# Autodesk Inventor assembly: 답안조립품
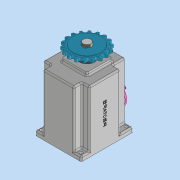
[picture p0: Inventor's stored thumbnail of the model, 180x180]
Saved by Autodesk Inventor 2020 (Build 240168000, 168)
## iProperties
Created: 2022-01
Part Number: 답안조립품
Document SubType Name: Assembly
Designer: user
Author: user
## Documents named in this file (16)
- C:\Users\user\Desktop\720112V1009\답안조립품.iam
- C:\Users\user\Desktop\720112V1009\멈춤나사 M3.ipt
- C:\Users\user\Desktop\720112V1009\메인 축.ipt
- C:\Users\user\Desktop\720112V1009\베어링 608.ipt
- C:\Users\user\Desktop\720112V1009\베어링 6003.ipt
- C:\Users\user\Desktop\720112V1009\본체.ipt
- C:\Users\user\Desktop\720112V1009\볼트 M4 x 10.ipt
- C:\Users\user\Desktop\720112V1009\부시.ipt
- C:\Users\user\Desktop\720112V1009\상부 캡.ipt
- C:\Users\user\Desktop\720112V1009\서브 축.ipt
- C:\Users\user\Desktop\720112V1009\스프로킷.ipt
- C:\Users\user\Desktop\720112V1009\슬라이더.ipt
- C:\Users\user\Desktop\720112V1009\오일 실 8 x 22 x 7.ipt
- C:\Users\user\Desktop\720112V1009\오일 실 17 x 32 x 8.ipt
- C:\Users\user\Desktop\720112V1009\커버.ipt
- C:\Users\user\Desktop\720112V1009\키 5 x 5.ipt
